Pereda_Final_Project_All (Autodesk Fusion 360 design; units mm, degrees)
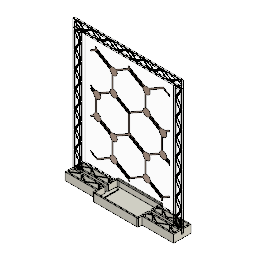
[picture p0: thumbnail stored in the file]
parameter "ScreenLength" = 305
parameter "ScreenWidth" = 236
parameter "ThicknessBase" = 20
parameter "ThicknessStand" = 5
parameter "WidthStandVertical" = 20
parameter "LengthStand" = 338 (= "ScreenLength + WidthStandVertical + ThicknessBase / 2 + Cutout")
parameter "WidthStandHorizontal" = 276 (= "ScreenWidth + WidthStandVertical * 2")
parameter "Cutout" = 3 (= "ThicknessStand * 0.6")
parameter "WidthBase" = 40 (= "ThicknessBase * 2")
parameter "LengthBase" = 276 (= "WidthStandHorizontal")
parameter "HoleStand" = 10 (= "ThicknessBase / 2")
sketch "Sketch1"
  dimension "d1" = 305 (= "ScreenLength")
  dimension "d4" = 236 (= "ScreenWidth")
  dimension "d9" = 338 (= "LengthStand")
  dimension "d12" = 20 (= "WidthStandVertical")
  dimension "d17" = 276 (= "WidthStandHorizontal")
  dimension "d18" = 338 (= "LengthStand")
  dimension "UnPleg" = 44.0208
  dimension "d27" = 44.021
  dimension "d28" = 0
  dimension "d31" = 44.021
  dimension "d32" = 0
  dimension "d33" = 44.0208
  dimension "d36" = 44.021
  dimension "d37" = 0
  dimension "d40" = 44.021
  dimension "d41" = 0
  dimension "d42" = 44.0208
  dimension "d43" = 44.0208
  dimension "d46" = 44.021
  dimension "d47" = 0
  dimension "d50" = 44.021
  dimension "d51" = 0
  dimension "d52" = 44.0208
  dimension "d53" = 44.0208
  dimension "d91" = 44.021
  dimension "d92" = 0
  dimension "d95" = 44.021
  dimension "d96" = 0
  dimension "d97" = 276 (= "WidthStandHorizontal")
  dimension "d98" = 44.0208
  dimension "d99" = 44.0208
  dimension "d117" = 44.0208
  dimension "d118" = 44.0208
  dimension "d120" = 44.0208
  dimension "d121" = 44.0208
  dimension "d122" = 3 (= "Cutout")
sketch "Sketch3"
extrude "Extrude3" new body sketch "Sketch1" blind 5 (= "ThicknessStand")
extrude "Extrude2" new body sketch "Sketch1" blind 5 (= "ThicknessStand")
extrude "Extrude1" new body sketch "Sketch1" blind 5 (= "ThicknessStand")
sketch "Sketch2" plane through (0, 0, 5) normal (0, 0, 1) x axis (-1, 0, 0)
  dimension "d58" = 44.0208
component_from_bodies "Body->Comp1"
move "Move1"
component_from_bodies "Body->Comp2"
position "Position1"
work_plane "WorkPlane1"
mirror_component "MirrorComponent1"
derived_instance "DerivedInstance1"
mirror "Mirror1"
remove_instance "RemoveInstance1"
position "Position2"
mirror_component "MirrorComponent2"
derived_instance "DerivedInstance2"
position "Position3"
position "Position4"
combine "Combine1"
sketch "Basefor3D&LaserCutting"
  dimension "d64" = 40 (= "WidthBase")
  dimension "d65" = 276 (= "LengthBase")
  dimension "d66" = 5 (= "ThicknessStand")
  dimension "d67" = 20 (= "WidthStandVertical")
  dimension "d68" = 115
  dimension "d69" = 65
  dimension "d70" = 109
  dimension "d71" = 59
  dimension "d72" = 115
  dimension "d73" = 65
  dimension "d74" = 105
  dimension "d75" = 55
  dimension "d148" = 115
  dimension "d149" = 65
  dimension "d150" = 105
  dimension "d151" = 55
  dimension "d152" = 2
  dimension "d153" = 2
extrude "Extrude4" new body sketch "Basefor3D&LaserCutting" blind 20 (= "ThicknessBase") bodies "3D Printed Base"
sketch "BaseHOle"
  dimension "d78" = 5 (= "ThicknessStand")
  dimension "d79" = 20 (= "WidthStandVertical")
extrude "Extrude6" cut sketch "BaseHOle" blind 10 (= "HoleStand")
extrude "Extrude5" cut sketch "BaseHOle" blind 17 (= "ThicknessBase - 3 mm")
move "Move1" RotateAngle 180
component_from_bodies "Body->Comp3"
fillet "Fillet1" radius 2
fillet "Fillet2" radius 2
delete_face "DeleteFace1"
split "Split1" bodies "EXTRABIT"
delete_face "DeleteFace1"
sketch "forRhino1" plane through (0, 0, 0) normal (0, 0, -1) x axis (1, 0, 0)
work_plane "WorkPlane4" AlongDistance 0
work_plane "WorkPlane5" AlongDistance 0
split "Split1" bodies "OriginalSide1"
split "Split2" bodies "OriginalSide2"
copy_paste_bodies "CopyPasteBodies1"
copy_paste_bodies "CopyPasteBodies3"
move "Move3"
copy_paste_bodies "CopyPasteBodies4"
move "Move4"
move "Move5"
align "Align1"
align "Align2"
align "Align1"
align "Align3"
align "Align4"
align "Align5"
align "Align6"
work_plane "WorkPlane6" AlongDistance 7.947
split "Split1" bodies "toolforbase (2)", "toolforbase (1) (1)"
split "Split2" bodies "toolforbase (1) (2)", "toolforbase (1) (3)", "toolforbase (3)", "toolforbase (4)"
offset_faces "OffsetFaces1" distance 15
combine "Combine1" bodies "3D Printed Base (2)", "3D Printed Base (2) (1)", "3D Printed Base (2) (2)", "3D Printed Base (2) (3)", "3D Printed Base (2) (4)", "MiddlePartStrip", "3D Printed Base (2) (6)", "3D Printed Base (2) (7)"
component_from_bodies "Body->Comp4"
component_from_bodies "Body->Comp5"
component_from_bodies "Body->Comp6"
component_from_bodies "Body->Comp7"
component_from_bodies "Body->Comp8"
component_from_bodies "Body->Comp9"
component_from_bodies "Body->Comp1"
combine "Combine1" bodies "toolforbase (1)", "toolforbase (2)", "toolforbase (3)"
extrude "Extrude1" add of existing geometry to an object bodies "toolforbase", "toolforbase (1)", "toolforbase (2)"
combine "Combine2"
combine "Combine1" bodies "toolforbase (3)"
combine "Combine1" bodies "3D Printed Base (3)"
mirror "Mirror1" bodies "3D Printed Base (3) (1)"
combine "Combine1" bodies "tiny side platfom"
mirror_component "MirrorComponent3"
derived_instance "DerivedInstance3"
combine "Combine2"
work_plane "WorkPlane7" AlongDistance 0
work_plane "WorkPlane8" AlongDistance 0
split "Split4" bodies "3D Printed Base (3) (2)", "3D Printed Base (3) (1)"
split "Split5" bodies "3D Printed Base (3) (1) (1)", "MiddleRectangle"
combine "Combine2"
combine "Combine1"
offset_faces "OffsetFaces1" distance 0.4
combine "Combine3"
offset_faces "OffsetFaces2" distance -0.4
extrude "Extrude1" cut of existing geometry blind -0.4
combine "Combine4"
delete_face "DeleteFace1"
combine "Combine5"
mirror_component "MirrorComponent4"
derived_instance "DerivedInstance4"
move "Move6"
move "Move7"
move "Move8"
align "Align7"
mirror "Mirror2"
sketch "toptrus" plane through (-150, 0, 590) normal (0, 1, 0) x axis (1, 0, 0)
place_component sketch "toptrus"
extrude "Extrude1" new body sketch "toptrus" along normal blind 5 (= "ThicknessStand")
ground "Ground1"
ground "Ground2"
position "Position5"
sketch "CopperTRaces" plane through (0, 0, 0) normal (0, 1, 0) x axis (1, 0, 0)
extrude "Extrude1" new body sketch "CopperTRaces" along normal blind 0.05
sketch "Sketch9" plane through (0, 0, 0) normal (0, 1, 0) x axis (1, 0, 0)
  dimension "d143" = 280
  dimension "d144" = 224
place_component sketch "Sketch9"
extrude "Extrude1" new body sketch "Sketch9" along normal blind 0.1
position "Position6"
ground "Ground3"
scale "Scale1" ScaleFactor 1.2
position "Position7"
combine "Combine1"
copy_paste_bodies "CutPasteBodies" sketch "toptrus"
combine "Combine1"
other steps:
base_feature "Base Feature1" bodies "toolforbase (1)"
base_feature "Base Feature1" bodies "toolforbase (1) (2)"
base_feature "Base Feature1" bodies "toolforbase (1) (3)"
base_feature "Base Feature1" bodies "toolforbase (3)"
base_feature "Base Feature1" bodies "toolforbase (4)"
base_feature "Base Feature1" bodies "MiddlePartStrip"
derived_base_feature "Derived Base Feature1" bodies "toolforbase (3)"
derived_base_feature "Derived Base Feature1"
derived_base_feature "Derived Base Feature1" bodies "toolforbase (3)"
base_feature "Base Feature1" sketch "toptrus" bodies "extra top truss"
base_feature "Base Feature1"
derived_base_feature "Derived Base Feature1"
base_feature "Base Feature1" bodies "toolforbase"
base_feature "Base Feature1"
base_feature "Base Feature1" bodies "3D Printed Base", "tiny side platfom"
split "Split3" bodies "3D Printed Base (3)"
base_feature "Base Feature1"
base_feature "Base Feature3" bodies "toolforbase"
base_feature "Base Feature4" bodies "toolforbase", "toolforbase (1)"
create_component "CreateComponent1"
remove_body "RemoveBody1"
create_component "CreateComponent2"
remove_body "RemoveBody2"
create_component "CreateComponent3"
create_component "CreateComponent4"
create_component "CreateComponent5"
remove_body "RemoveBody3"
create_component "CreateComponent7"
create_component "CreateComponent8"
remove_body "RemoveBody5"
create_component "CreateComponent9"
remove_body "RemoveBody6"
create_component "CreateComponent10"
remove_body "RemoveBody7"
create_component "CreateComponent11"
remove_body "RemoveBody8"
create_component "CreateComponent12"
remove_body "RemoveBody9"
create_component "CreateComponent13"
remove_body "RemoveBody10"
create_component "CreateComponent1"
remove_body "RemoveBody1"
create_component "CreateComponent14"
create_component "CreateComponent15"
create_component "CreateComponent16"
remove_body "RemoveBody11"
create_component "CreateComponent17"
create_component "CreateComponent18" sketch "toptrus"
create_component "CreateComponent19"
create_component "CreateComponent20" sketch "Sketch9"
remove_body "RemoveBody12"
remove_body "RemoveBody13"
create_component "CreateComponent21"
named bodies: "3D Printed Base", "tiny side platfom", "EXTRABIT", "OriginalSide1", "OriginalSide2", "toolforbase", "toolforbase (1)", "toolforbase (2)", "toolforbase (1) (1)", "3D Printed Base (3)", "toolforbase (1) (2)", "toolforbase (1) (3)", "toolforbase (3)", "toolforbase (4)", "3D Printed Base (2)", "3D Printed Base (2) (1)", "3D Printed Base (2) (2)", "3D Printed Base (2) (3)", "3D Printed Base (2) (4)", "MiddlePartStrip", "3D Printed Base (2) (6)", "3D Printed Base (2) (7)", "3D Printed Base (2) (8)", "3D Printed Base (2) (9)", "3D Printed Base (2) (10)", "3D Printed Base (3) (1)", "3D Printed Base (3) (2)", "3D Printed Base (3) (1) (1)", "MiddleRectangle", "extra top truss"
